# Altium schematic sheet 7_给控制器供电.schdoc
size 309 x 223 mm; Symbol: Sheet-Symbol_A4; Device: Sheet-Symbol_A4; Company: 嘉立创EDA; Version: V1.0; Page Size: A4; @Project Name: 共享电动车中控; @Page Count: 11; @Update Date: 2024-11-20; @Create Date: 2024-09-26; @Schematic Name: SCH; @Page No: 7; @Page Name: 给控制器供电; @Board Name: STM32F103C8T6; @Create Time: 02:39:01; @Update Time: 16:43:35
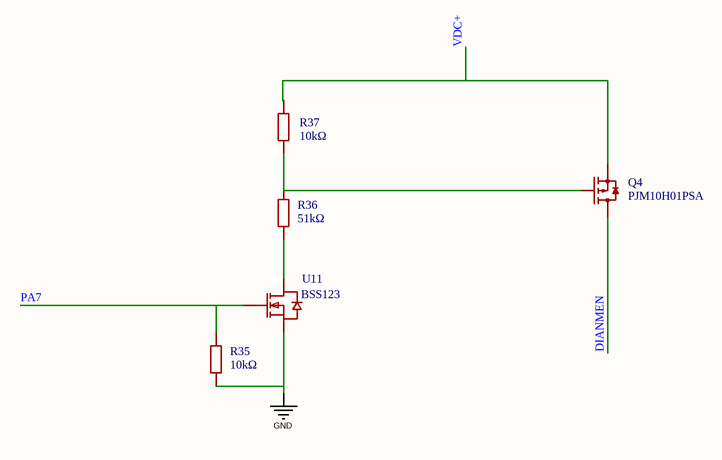
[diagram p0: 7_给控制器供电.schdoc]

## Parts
Q4  PJM10H01PSA  [SOT-23-3_L2.9-W1.3-P0.95-LS2.4-BR]  (value not drawn)
R35  10kΩ  [R0805]
R36  51kΩ  [R0805]  (value not drawn)
R37  10kΩ  [R0805]
U11  BSS123  [SOT-23-3_L2.9-W1.3-P1.90-LS2.4-BR]  (value not drawn)

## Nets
GND: R35.2 U11.2(S)
DIANMEN: Q4.3(D)
PA7: R35.1 U11.1(G)
VDC+: Q4.2(S) R37.1
NetQ4_1: Q4.1(G) R36.2 R37.2
NetR36_1: R36.1 U11.3(D)

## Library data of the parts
Q4 = PJM10H01PSA: 类型:1个P沟道;漏源电压(Vdss):100V;连续漏极电流(Id):1A;功率(Pd):500mW;导通电阻(RDS(on)@Vgs,Id):650mΩ@10V,1A;阈值电压(Vgs(th)@Id):2.5V@250uA;; Manufacturer: PJSEMI(平晶微); Add into BOM: yes; Type: 1个P沟道; Drain Source Voltage (Vdss): 100V; Power Dissipation (Pd): 500mW; Total Gate Charge (Qg@Vgs): 4nC@10V
R35 R37 = 0805W8F1002T5E_C17414: 电阻类型:厚膜电阻;阻值:10kΩ;精度:±1%;功率:125mW;最大工作电压:150V;温度系数:±100ppm/℃;; Manufacturer: UNI-ROYAL(厚声); Symbol: RC0402FR-0710KL; Add into BOM: yes; Tolerance: ±1%; Power(Watts): 125mW; Overload Voltage (Max): 150V
R36 = 0805W8F5102T5E: 电阻类型:厚膜电阻;阻值:51kΩ;精度:±1%;功率:125mW;最大工作电压:150V;温度系数:±100ppm/℃;; Manufacturer: UNI-ROYAL(厚声); Symbol: 0603WAF5102T5E; Add into BOM: yes; Tolerance: ±1%; Power(Watts): 125mW; Overload Voltage (Max): 150V
U11 = BSS123_C7420338: 类型:N沟道;漏源电压(Vdss):100V;连续漏极电流(Id):200mA;功率(Pd):350mW;导通电阻(RDS(on)@Vgs,Id):5Ω@10V,0.2A;阈值电压(Vgs(th)@Id):2.5V@250uA;; Manufacturer: 宏迦橙; Add into BOM: yes; Drain Source Voltage (Vdss): 100V; Continuous Drain Current (Id): 200mA; Power Dissipation (Pd): 350mW; Total Gate Charge (Qg@Vgs): 1.4nC@10V; Input Capacitance (Ciss@Vds): 32pF@50V; Reverse Transfer Capacitance (Crss@Vds): 7pF@50V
